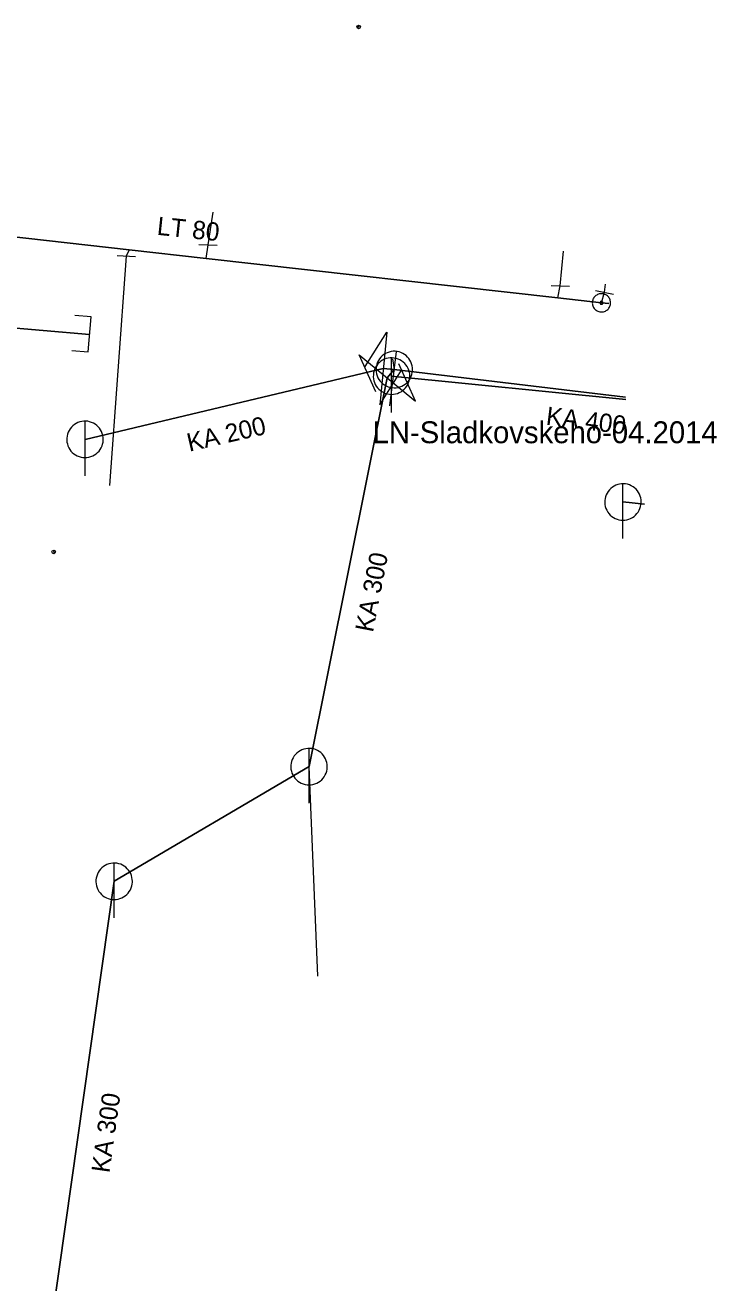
# Model space of a CAD drawing. Extents: x -783064 to -782702, y -1007904 to -1007145.
# Drawn here: x -782753.5 to -782715.6, y -1007626.6 to -1007557.6 of the extents above; entities that cross this region are included whole.
import ezdxf

# ---------------------------------------------------------------- set-up
doc = ezdxf.new("R2010")
doc.units = 0
doc.header["$LTSCALE"] = 0.4
doc.header["$PDMODE"] = 32
doc.header["$PDSIZE"] = 0.2
for name, color, linetype, lineweight in [('1', 7, 'Continuous', 13), ('11', 7, 'Continuous', 13), ('13', 7, 'Continuous', 13), ('14', 7, 'Continuous', 13), ('17', 7, 'Continuous', 25), ('22', 7, 'Continuous', 13), ('31', 7, 'Continuous', 13), ('34', 7, 'Continuous', 13), ('47', 7, 'Continuous', 13)]:
    doc.layers.add(name, color=color, linetype=linetype, lineweight=lineweight)

msp = doc.modelspace()

# ---------------------------------------------------------------- linework, layer by layer
at = {"layer": '1'}
for p in [(-782735.25, -1007557.709), (-782751.96, -1007586.489)]:
    msp.add_point(p, dxfattribs=at)
at = {"layer": '11'}
for p, q in [((-782733.399, -1007575.9), (-782733.3, -1007576.49)), ((-782737.495, -1007609.743), (-782737.969, -1007598.26))]:
    msp.add_line(p, q, dxfattribs=at)
at = {"layer": '13'}
for p, q in [((-782743.502, -1007569.654), (-782743.213, -1007567.863)), ((-782747.826, -1007569.923), (-782747.981, -1007570.267)), ((-782743.599, -1007570.399), (-782743.502, -1007569.654)), ((-782747.981, -1007570.267), (-782748.909, -1007582.857))]:
    msp.add_line(p, q, dxfattribs=at)
msp.add_lwpolyline([(-782724.344, -1007572.563), (-782724.201, -1007571.908), (-782724.028, -1007570.001)], dxfattribs=at)
at = {"layer": '14'}
for p, q in [((-782721.774, -1007572.255), (-782721.731, -1007571.818)), ((-782721.948, -1007572.833), (-782721.774, -1007572.255))]:
    msp.add_line(p, q, dxfattribs=at)
at = {"layer": '14', "lineweight": 25}
for p, q in [((-782749.991, -1007574.563), (-782769.09, -1007572.93)), ((-782750.244, -1007580.319), (-782733.899, -1007576.43)), ((-782733.899, -1007576.43), (-782733.3, -1007576.49)), ((-782733.68, -1007576.95), (-782733.3, -1007576.49)), ((-782733.449, -1007576.85), (-782720.607, -1007578.138)), ((-782733.3, -1007576.49), (-782720.631, -1007578.005)), ((-782737.969, -1007598.26), (-782733.68, -1007576.95)), ((-782720.77, -1007583.75), (-782719.589, -1007583.864)), ((-782748.649, -1007604.55), (-782737.969, -1007598.26)), ((-782752.26, -1007630.1), (-782748.649, -1007604.55))]:
    msp.add_line(p, q, dxfattribs=at)
at = {"layer": '17'}
msp.add_line((-782721.543, -1007572.876), (-782721.948, -1007572.833), dxfattribs=at)
msp.add_lwpolyline([(-782721.948, -1007572.833), (-782724.344, -1007572.563), (-782743.599, -1007570.399), (-782747.826, -1007569.923), (-782765.967, -1007567.884), (-782794.359, -1007564.46)], dxfattribs=at)
at = {"layer": '22'}
for p, q in [((-782733.538, -1007578.476), (-782733.18, -1007575.497)), ((-782733.449, -1007578.85), (-782733.448, -1007575.85)), ((-782750.244, -1007582.319), (-782750.243, -1007579.319)), ((-782720.77, -1007585.75), (-782720.769, -1007582.75)), ((-782737.969, -1007600.26), (-782737.968, -1007597.26)), ((-782748.649, -1007606.55), (-782748.648, -1007603.55))]:
    msp.add_line(p, q, dxfattribs=at)
for points in [[(-782732.307, -1007576.609), (-782732.3, -1007576.5), (-782732.305, -1007576.391), (-782732.322, -1007576.282), (-782732.349, -1007576.177), (-782732.389, -1007576.075), (-782732.44, -1007575.978), (-782732.502, -1007575.887), (-782732.572, -1007575.804), (-782732.652, -1007575.728), (-782732.739, -1007575.662), (-782732.833, -1007575.605), (-782732.933, -1007575.56), (-782733.037, -1007575.525), (-782733.144, -1007575.503), (-782733.253, -1007575.491), (-782733.362, -1007575.492), (-782733.471, -1007575.504), (-782733.578, -1007575.529), (-782733.681, -1007575.566), (-782733.779, -1007575.612), (-782733.873, -1007575.671), (-782733.959, -1007575.738), (-782734.037, -1007575.815), (-782734.107, -1007575.899), (-782734.166, -1007575.991), (-782734.215, -1007576.089), (-782734.254, -1007576.192), (-782734.281, -1007576.298), (-782734.296, -1007576.407), (-782734.299, -1007576.516), (-782734.291, -1007576.625), (-782734.269, -1007576.732), (-782734.238, -1007576.837), (-782734.194, -1007576.937), (-782734.139, -1007577.033), (-782734.075, -1007577.121), (-782734.002, -1007577.202), (-782733.92, -1007577.275), (-782733.831, -1007577.338), (-782733.734, -1007577.391), (-782733.633, -1007577.433), (-782733.528, -1007577.464), (-782733.42, -1007577.483), (-782733.311, -1007577.49), (-782733.202, -1007577.485), (-782733.094, -1007577.469), (-782732.988, -1007577.44), (-782732.885, -1007577.4), (-782732.788, -1007577.349), (-782732.698, -1007577.289), (-782732.614, -1007577.218), (-782732.539, -1007577.138), (-782732.472, -1007577.052), (-782732.416, -1007576.958), (-782732.37, -1007576.859), (-782732.335, -1007576.754), (-782732.312, -1007576.647)], [(-782732.449, -1007576.85), (-782732.454, -1007576.741), (-782732.472, -1007576.633), (-782732.502, -1007576.527), (-782732.542, -1007576.426), (-782732.594, -1007576.329), (-782732.656, -1007576.239), (-782732.728, -1007576.156), (-782732.808, -1007576.082), (-782732.896, -1007576.016), (-782732.99, -1007575.961), (-782733.09, -1007575.916), (-782733.195, -1007575.883), (-782733.302, -1007575.861), (-782733.411, -1007575.851), (-782733.521, -1007575.853), (-782733.629, -1007575.867), (-782733.736, -1007575.892), (-782733.839, -1007575.929), (-782733.937, -1007575.978), (-782734.029, -1007576.036), (-782734.115, -1007576.105), (-782734.192, -1007576.182), (-782734.261, -1007576.268), (-782734.32, -1007576.36), (-782734.368, -1007576.458), (-782734.405, -1007576.561), (-782734.431, -1007576.668), (-782734.445, -1007576.776), (-782734.448, -1007576.886), (-782734.438, -1007576.995), (-782734.417, -1007577.102), (-782734.383, -1007577.206), (-782734.339, -1007577.306), (-782734.284, -1007577.401), (-782734.218, -1007577.489), (-782734.144, -1007577.569), (-782734.061, -1007577.641), (-782733.971, -1007577.703), (-782733.875, -1007577.755), (-782733.773, -1007577.796), (-782733.668, -1007577.826), (-782733.56, -1007577.844), (-782733.45, -1007577.85), (-782733.341, -1007577.844), (-782733.233, -1007577.826), (-782733.128, -1007577.797), (-782733.026, -1007577.756), (-782732.929, -1007577.704), (-782732.839, -1007577.642), (-782732.756, -1007577.571), (-782732.681, -1007577.491), (-782732.616, -1007577.403), (-782732.56, -1007577.309), (-782732.516, -1007577.209), (-782732.482, -1007577.105), (-782732.46, -1007576.997), (-782732.45, -1007576.888)], [(-782749.244, -1007580.319), (-782749.249, -1007580.21), (-782749.267, -1007580.102), (-782749.297, -1007579.996), (-782749.337, -1007579.895), (-782749.389, -1007579.798), (-782749.451, -1007579.708), (-782749.523, -1007579.625), (-782749.603, -1007579.551), (-782749.691, -1007579.485), (-782749.785, -1007579.43), (-782749.885, -1007579.385), (-782749.99, -1007579.352), (-782750.097, -1007579.33), (-782750.206, -1007579.32), (-782750.316, -1007579.322), (-782750.424, -1007579.336), (-782750.531, -1007579.361), (-782750.634, -1007579.398), (-782750.732, -1007579.447), (-782750.824, -1007579.505), (-782750.91, -1007579.574), (-782750.987, -1007579.651), (-782751.056, -1007579.737), (-782751.115, -1007579.829), (-782751.163, -1007579.927), (-782751.2, -1007580.03), (-782751.226, -1007580.137), (-782751.24, -1007580.245), (-782751.243, -1007580.355), (-782751.233, -1007580.464), (-782751.212, -1007580.571), (-782751.178, -1007580.675), (-782751.134, -1007580.775), (-782751.079, -1007580.87), (-782751.013, -1007580.958), (-782750.939, -1007581.038), (-782750.856, -1007581.11), (-782750.766, -1007581.172), (-782750.67, -1007581.224), (-782750.568, -1007581.265), (-782750.463, -1007581.295), (-782750.355, -1007581.313), (-782750.245, -1007581.319), (-782750.136, -1007581.313), (-782750.028, -1007581.295), (-782749.923, -1007581.266), (-782749.821, -1007581.225), (-782749.724, -1007581.173), (-782749.634, -1007581.111), (-782749.551, -1007581.04), (-782749.476, -1007580.96), (-782749.411, -1007580.872), (-782749.355, -1007580.778), (-782749.311, -1007580.678), (-782749.277, -1007580.574), (-782749.255, -1007580.466), (-782749.245, -1007580.357)], [(-782719.77, -1007583.75), (-782719.775, -1007583.641), (-782719.793, -1007583.533), (-782719.823, -1007583.427), (-782719.863, -1007583.326), (-782719.915, -1007583.229), (-782719.977, -1007583.139), (-782720.049, -1007583.056), (-782720.129, -1007582.982), (-782720.217, -1007582.916), (-782720.311, -1007582.861), (-782720.411, -1007582.816), (-782720.516, -1007582.783), (-782720.623, -1007582.761), (-782720.732, -1007582.751), (-782720.842, -1007582.753), (-782720.95, -1007582.767), (-782721.057, -1007582.792), (-782721.16, -1007582.829), (-782721.258, -1007582.878), (-782721.35, -1007582.936), (-782721.436, -1007583.005), (-782721.513, -1007583.082), (-782721.582, -1007583.168), (-782721.641, -1007583.26), (-782721.689, -1007583.358), (-782721.726, -1007583.461), (-782721.752, -1007583.568), (-782721.766, -1007583.676), (-782721.769, -1007583.786), (-782721.759, -1007583.895), (-782721.738, -1007584.002), (-782721.704, -1007584.106), (-782721.66, -1007584.206), (-782721.605, -1007584.301), (-782721.539, -1007584.389), (-782721.465, -1007584.469), (-782721.382, -1007584.541), (-782721.292, -1007584.603), (-782721.196, -1007584.655), (-782721.094, -1007584.696), (-782720.989, -1007584.726), (-782720.881, -1007584.744), (-782720.771, -1007584.75), (-782720.662, -1007584.744), (-782720.554, -1007584.726), (-782720.449, -1007584.697), (-782720.347, -1007584.656), (-782720.25, -1007584.604), (-782720.16, -1007584.542), (-782720.077, -1007584.471), (-782720.002, -1007584.391), (-782719.937, -1007584.303), (-782719.881, -1007584.209), (-782719.837, -1007584.109), (-782719.803, -1007584.005), (-782719.781, -1007583.897), (-782719.771, -1007583.788)], [(-782736.969, -1007598.26), (-782736.974, -1007598.151), (-782736.992, -1007598.043), (-782737.022, -1007597.937), (-782737.062, -1007597.836), (-782737.114, -1007597.739), (-782737.176, -1007597.649), (-782737.248, -1007597.566), (-782737.328, -1007597.492), (-782737.416, -1007597.426), (-782737.51, -1007597.371), (-782737.61, -1007597.326), (-782737.715, -1007597.293), (-782737.822, -1007597.271), (-782737.931, -1007597.261), (-782738.041, -1007597.263), (-782738.149, -1007597.277), (-782738.256, -1007597.302), (-782738.359, -1007597.339), (-782738.457, -1007597.388), (-782738.549, -1007597.446), (-782738.635, -1007597.515), (-782738.712, -1007597.592), (-782738.781, -1007597.678), (-782738.84, -1007597.77), (-782738.888, -1007597.868), (-782738.925, -1007597.971), (-782738.951, -1007598.078), (-782738.965, -1007598.186), (-782738.968, -1007598.296), (-782738.958, -1007598.405), (-782738.937, -1007598.512), (-782738.903, -1007598.616), (-782738.859, -1007598.716), (-782738.804, -1007598.811), (-782738.738, -1007598.899), (-782738.664, -1007598.979), (-782738.581, -1007599.051), (-782738.491, -1007599.113), (-782738.395, -1007599.165), (-782738.293, -1007599.206), (-782738.188, -1007599.236), (-782738.08, -1007599.254), (-782737.97, -1007599.26), (-782737.861, -1007599.254), (-782737.753, -1007599.236), (-782737.648, -1007599.207), (-782737.546, -1007599.166), (-782737.449, -1007599.114), (-782737.359, -1007599.052), (-782737.276, -1007598.981), (-782737.201, -1007598.901), (-782737.136, -1007598.813), (-782737.08, -1007598.719), (-782737.036, -1007598.619), (-782737.002, -1007598.515), (-782736.98, -1007598.407), (-782736.97, -1007598.298)], [(-782747.649, -1007604.55), (-782747.654, -1007604.441), (-782747.672, -1007604.333), (-782747.702, -1007604.227), (-782747.742, -1007604.126), (-782747.794, -1007604.029), (-782747.856, -1007603.939), (-782747.928, -1007603.856), (-782748.008, -1007603.782), (-782748.096, -1007603.716), (-782748.19, -1007603.661), (-782748.29, -1007603.616), (-782748.395, -1007603.583), (-782748.502, -1007603.561), (-782748.611, -1007603.551), (-782748.721, -1007603.553), (-782748.829, -1007603.567), (-782748.936, -1007603.592), (-782749.039, -1007603.629), (-782749.137, -1007603.678), (-782749.229, -1007603.736), (-782749.315, -1007603.805), (-782749.392, -1007603.882), (-782749.461, -1007603.968), (-782749.52, -1007604.06), (-782749.568, -1007604.158), (-782749.605, -1007604.261), (-782749.631, -1007604.368), (-782749.645, -1007604.476), (-782749.648, -1007604.586), (-782749.638, -1007604.695), (-782749.617, -1007604.802), (-782749.583, -1007604.906), (-782749.539, -1007605.006), (-782749.484, -1007605.101), (-782749.418, -1007605.189), (-782749.344, -1007605.269), (-782749.261, -1007605.341), (-782749.171, -1007605.403), (-782749.075, -1007605.455), (-782748.973, -1007605.496), (-782748.868, -1007605.526), (-782748.76, -1007605.544), (-782748.65, -1007605.55), (-782748.541, -1007605.544), (-782748.433, -1007605.526), (-782748.328, -1007605.497), (-782748.226, -1007605.456), (-782748.129, -1007605.404), (-782748.039, -1007605.342), (-782747.956, -1007605.271), (-782747.881, -1007605.191), (-782747.816, -1007605.103), (-782747.76, -1007605.009), (-782747.716, -1007604.909), (-782747.682, -1007604.805), (-782747.66, -1007604.697), (-782747.65, -1007604.588)]]:
    msp.add_lwpolyline(points, close=True, dxfattribs=at)
at = {"layer": '31'}
for points in [[(-782750.972, -1007575.446), (-782750.074, -1007575.525), (-782749.906, -1007573.6), (-782750.803, -1007573.522)], [(-782734.894, -1007576.33), (-782733.7, -1007574.44), (-782734.098, -1007578.42), (-782732.904, -1007576.53)], [(-782734.316, -1007577.721), (-782735.221, -1007575.676), (-782732.137, -1007578.224), (-782733.042, -1007576.179)]]:
    msp.add_lwpolyline(points, dxfattribs=at)
at = {"layer": '34'}
for p, q in [((-782744.001, -1007569.634), (-782743.002, -1007569.674)), ((-782748.48, -1007570.247), (-782747.481, -1007570.287)), ((-782724.7, -1007571.888), (-782723.701, -1007571.928)), ((-782722.264, -1007572.157), (-782721.283, -1007572.353))]:
    msp.add_line(p, q, dxfattribs=at)
at = {"layer": '47'}
for points in [[(-782721.449, -1007572.873), (-782721.448, -1007572.821), (-782721.452, -1007572.768), (-782721.462, -1007572.717), (-782721.476, -1007572.667), (-782721.496, -1007572.618), (-782721.521, -1007572.572), (-782721.551, -1007572.53), (-782721.585, -1007572.49), (-782721.622, -1007572.454), (-782721.663, -1007572.421), (-782721.708, -1007572.393), (-782721.756, -1007572.371), (-782721.804, -1007572.353), (-782721.856, -1007572.341), (-782721.907, -1007572.334), (-782721.959, -1007572.333), (-782722.012, -1007572.337), (-782722.064, -1007572.347), (-782722.113, -1007572.361), (-782722.162, -1007572.381), (-782722.208, -1007572.406), (-782722.251, -1007572.436), (-782722.291, -1007572.47), (-782722.327, -1007572.507), (-782722.359, -1007572.548), (-782722.387, -1007572.593), (-782722.41, -1007572.641), (-782722.427, -1007572.689), (-782722.439, -1007572.741), (-782722.446, -1007572.792), (-782722.447, -1007572.844), (-782722.443, -1007572.897), (-782722.434, -1007572.949), (-782722.419, -1007572.998), (-782722.399, -1007573.047), (-782722.375, -1007573.093), (-782722.345, -1007573.136), (-782722.311, -1007573.176), (-782722.273, -1007573.212), (-782722.232, -1007573.244), (-782722.187, -1007573.272), (-782722.14, -1007573.294), (-782722.091, -1007573.312), (-782722.039, -1007573.324), (-782721.988, -1007573.331), (-782721.936, -1007573.332), (-782721.883, -1007573.328), (-782721.832, -1007573.319), (-782721.782, -1007573.304), (-782721.733, -1007573.284), (-782721.687, -1007573.26), (-782721.645, -1007573.23), (-782721.605, -1007573.196), (-782721.569, -1007573.158), (-782721.536, -1007573.117), (-782721.508, -1007573.072), (-782721.487, -1007573.025), (-782721.468, -1007572.976), (-782721.456, -1007572.924)], [(-782721.866, -1007572.839), (-782721.865, -1007572.83), (-782721.866, -1007572.822), (-782721.868, -1007572.814), (-782721.87, -1007572.806), (-782721.873, -1007572.797), (-782721.878, -1007572.79), (-782721.882, -1007572.783), (-782721.888, -1007572.776), (-782721.894, -1007572.771), (-782721.901, -1007572.765), (-782721.909, -1007572.76), (-782721.916, -1007572.757), (-782721.924, -1007572.754), (-782721.932, -1007572.751), (-782721.941, -1007572.751), (-782721.95, -1007572.75), (-782721.958, -1007572.751), (-782721.966, -1007572.753), (-782721.974, -1007572.755), (-782721.983, -1007572.758), (-782721.99, -1007572.763), (-782721.997, -1007572.767), (-782722.004, -1007572.773), (-782722.01, -1007572.779), (-782722.015, -1007572.786), (-782722.02, -1007572.794), (-782722.023, -1007572.801), (-782722.026, -1007572.809), (-782722.029, -1007572.817), (-782722.029, -1007572.826), (-782722.03, -1007572.835), (-782722.029, -1007572.843), (-782722.027, -1007572.851), (-782722.025, -1007572.859), (-782722.022, -1007572.868), (-782722.018, -1007572.875), (-782722.013, -1007572.882), (-782722.007, -1007572.889), (-782722.001, -1007572.895), (-782721.994, -1007572.9), (-782721.986, -1007572.905), (-782721.979, -1007572.908), (-782721.971, -1007572.911), (-782721.963, -1007572.914), (-782721.954, -1007572.914), (-782721.945, -1007572.915), (-782721.937, -1007572.914), (-782721.929, -1007572.912), (-782721.921, -1007572.91), (-782721.912, -1007572.907), (-782721.905, -1007572.903), (-782721.898, -1007572.898), (-782721.891, -1007572.892), (-782721.886, -1007572.886), (-782721.88, -1007572.879), (-782721.875, -1007572.871), (-782721.872, -1007572.864), (-782721.869, -1007572.856), (-782721.866, -1007572.848)]]:
    msp.add_lwpolyline(points, close=True, dxfattribs=at)

# ---------------------------------------------------------------- texts
at = {"layer": '1'}
for s, rotation, p in [('LT 80 ', 354, (-782746.332, -1007569.099)), ('KA 400', 353, (-782725.019, -1007579.509)), ('KA 200', 13, (-782744.53, -1007580.999)), ('KA 300', 79, (-782734.469, -1007590.937)), ('KA 300', 82, (-782748.908, -1007620.572))]:
    msp.add_text(s, height=1, rotation=rotation, dxfattribs=at).set_placement(p)
msp.add_text('LN-Sladkovskeho-04.2014 ', height=1.2, dxfattribs=at).set_placement((-782734.489, -1007580.53))

doc.saveas('drawing.dxf')
